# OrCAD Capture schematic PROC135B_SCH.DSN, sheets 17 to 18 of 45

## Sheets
17 17. LPDDR4 INTERFACE: size C; title: SOC DDRSS AND LPDDR4 MEMORY DEVICE INTERFACE
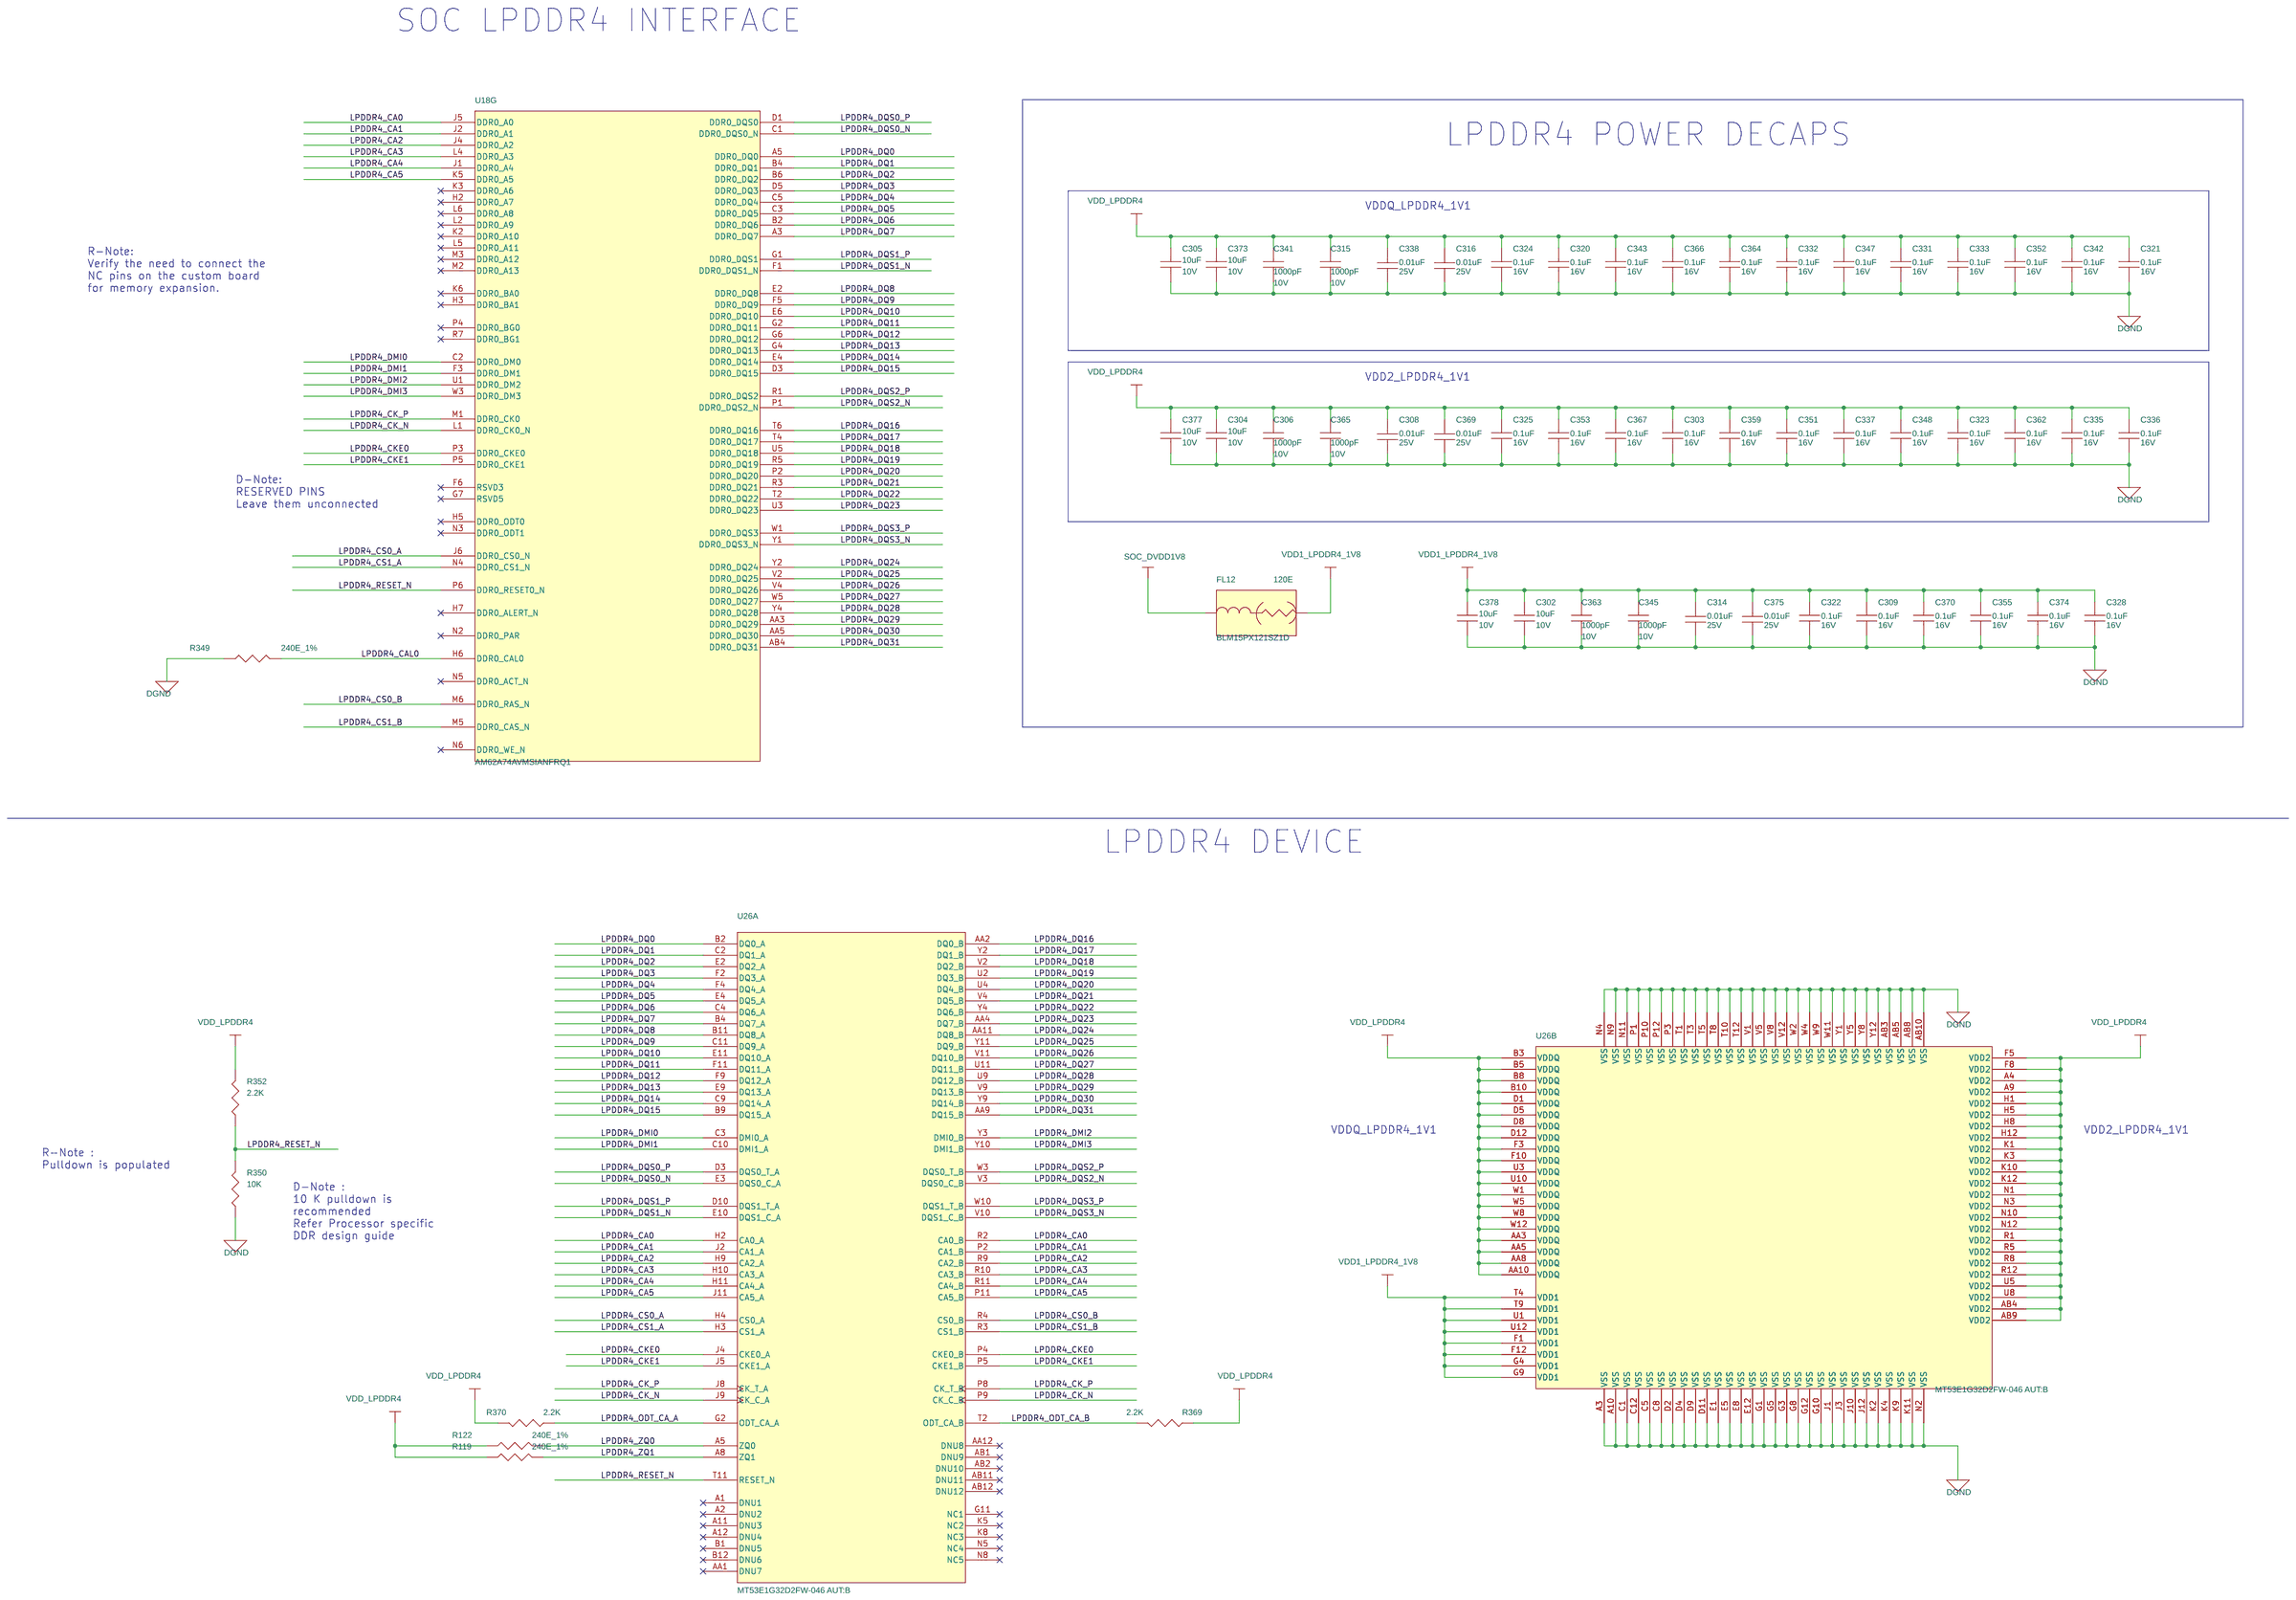
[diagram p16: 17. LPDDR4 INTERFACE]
18 18. M.2 CONNECTOR: size C; title: M.2 INTERFACE AND CONNECTOR
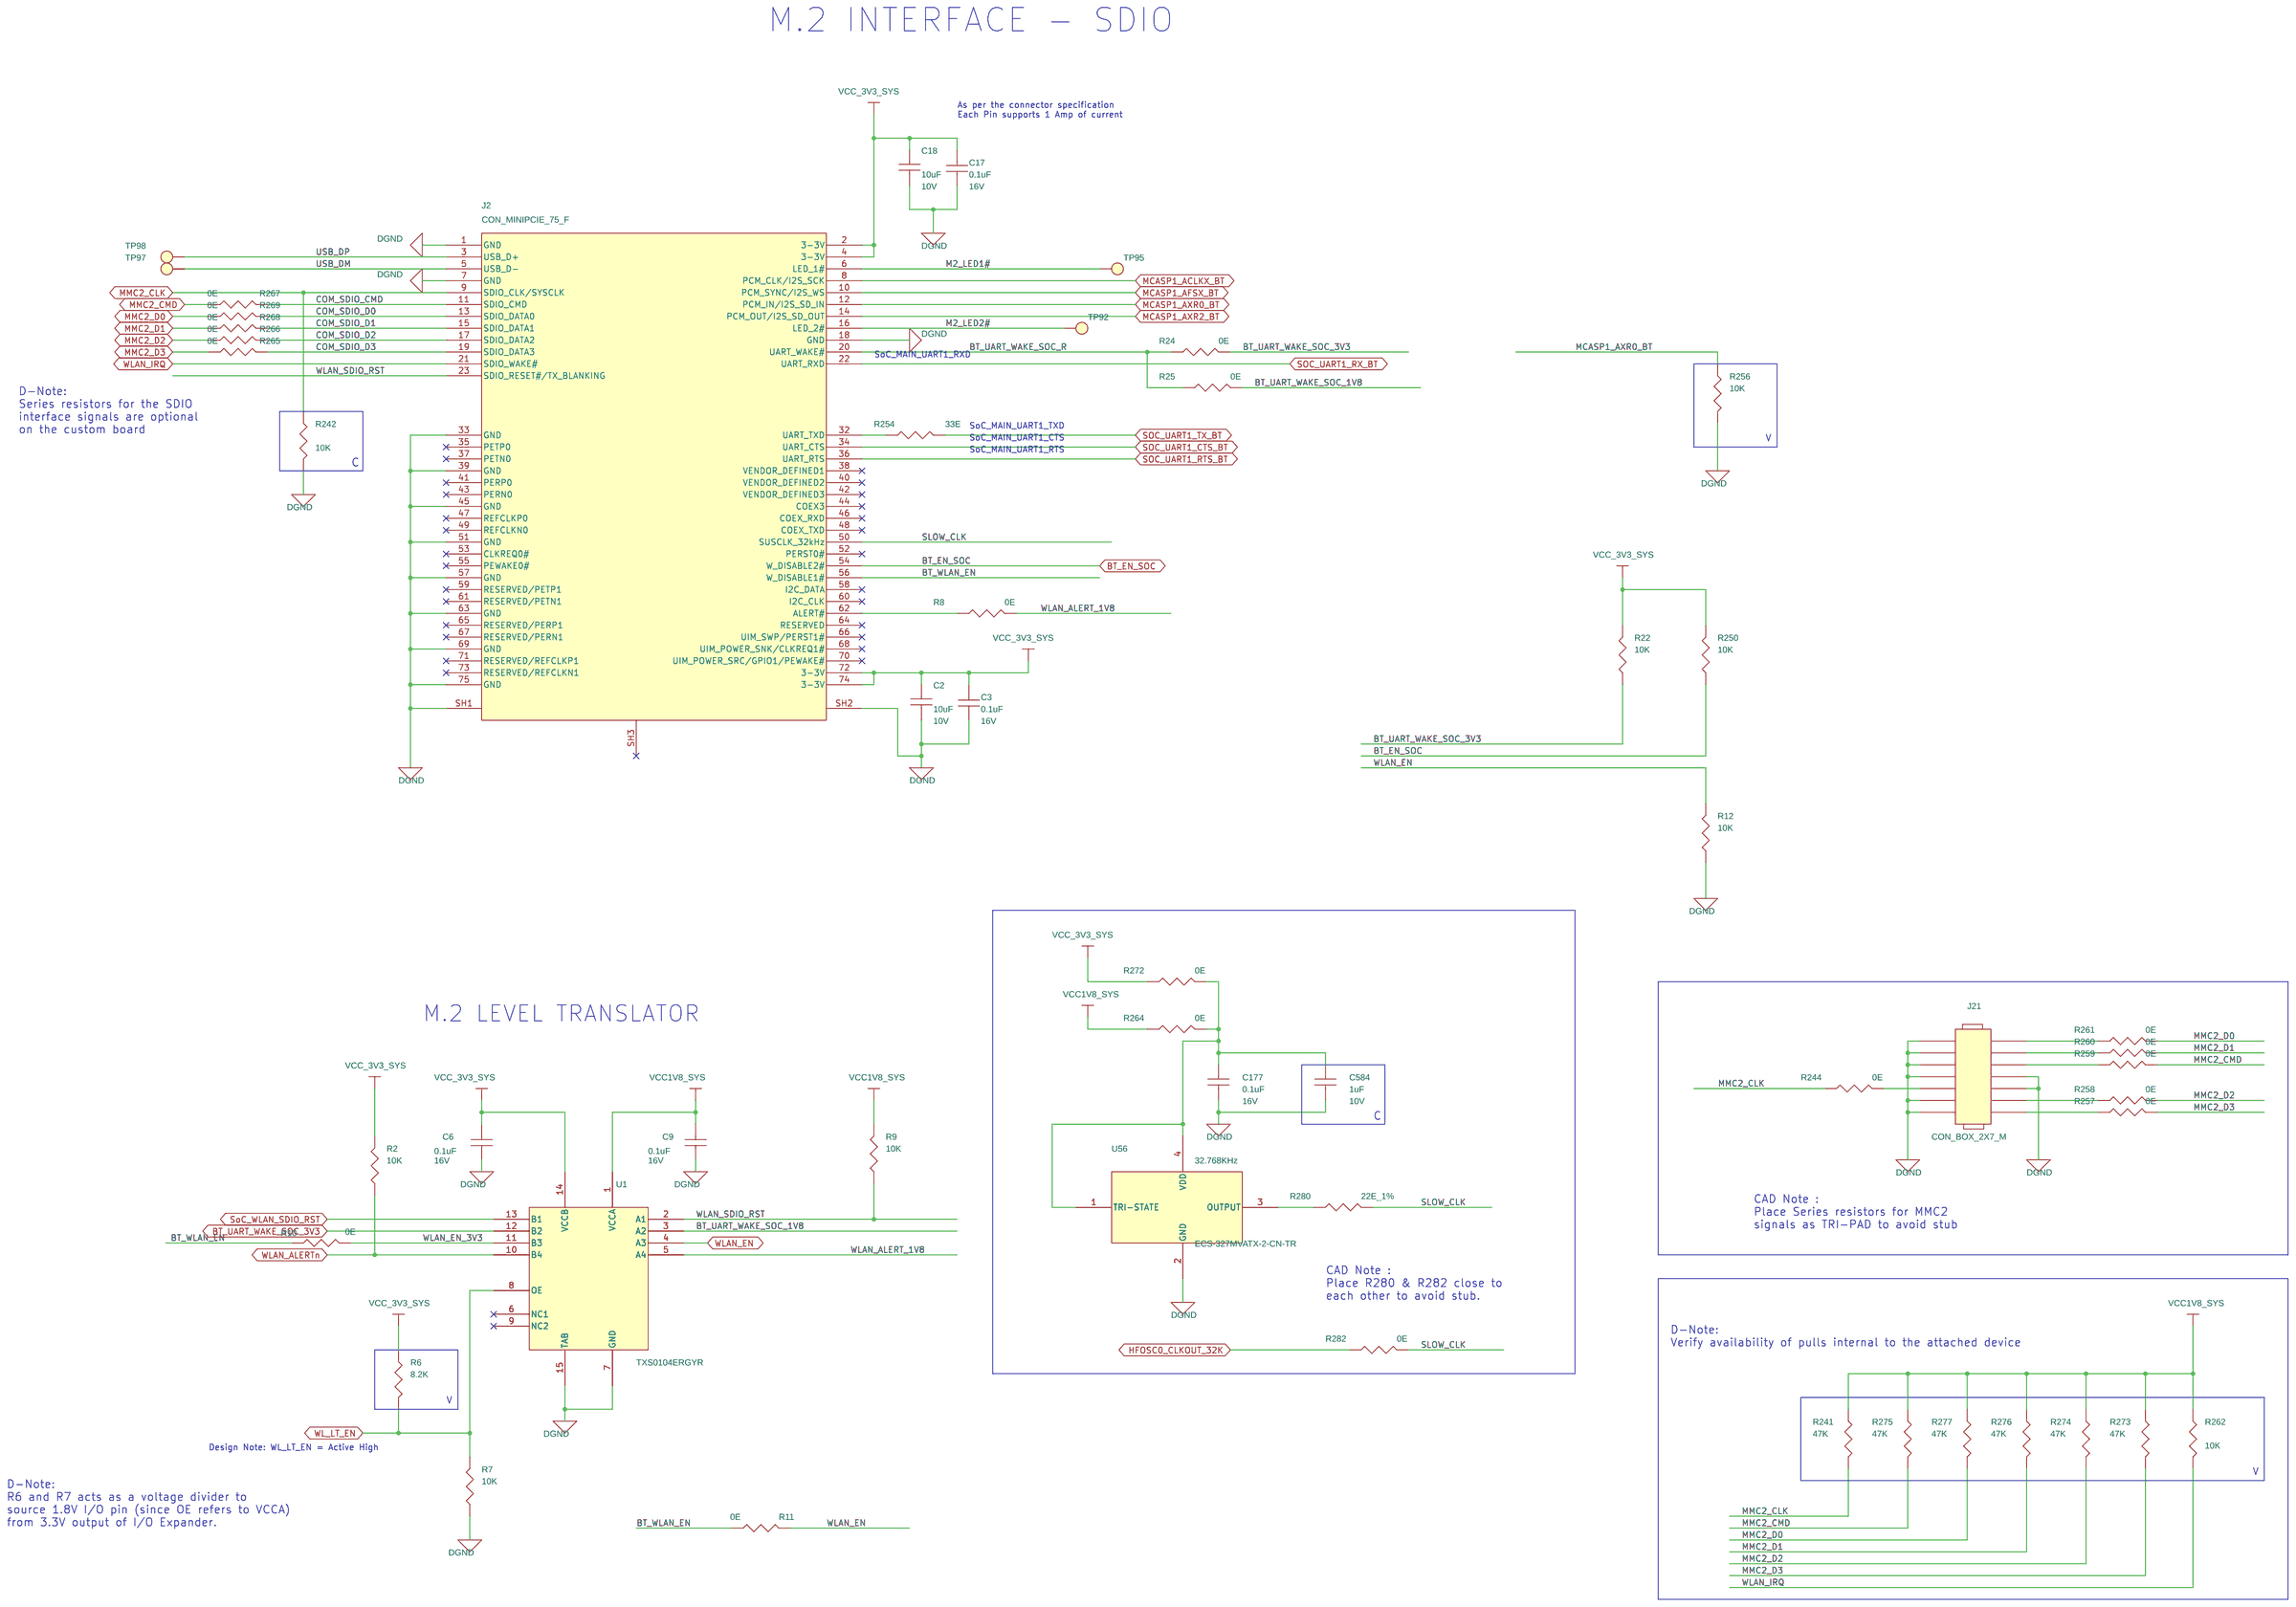
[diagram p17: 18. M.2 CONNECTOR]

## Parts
sheet 17. LPDDR4 INTERFACE
C302  10uF  [CAP0402_0-75]
C303  0.1uF  [CAP0201_0-5]
C304  10uF  [CAP0402_0-75]
C305  10uF  [CAP0402_0-75]
C306  1000pF  [CAP0201_0-5]
C308  0.01uF  [CAP0201_0-5]
C309  0.1uF  [CAP0201_0-5]
C314  0.01uF  [CAP0201_0-5]
C315  1000pF  [CAP0201_0-5]
C316  0.01uF  [CAP0201_0-5]
C320  0.1uF  [CAP0201_0-5]
C321  0.1uF  [CAP0201_0-5]
C322  0.1uF  [CAP0201_0-5]
C323  0.1uF  [CAP0201_0-5]
C324  0.1uF  [CAP0201_0-5]
C325  0.1uF  [CAP0201_0-5]
C328  0.1uF  [CAP0201_0-5]
C331  0.1uF  [CAP0201_0-5]
C332  0.1uF  [CAP0201_0-5]
C333  0.1uF  [CAP0201_0-5]
C335  0.1uF  [CAP0201_0-5]
C336  0.1uF  [CAP0201_0-5]
C337  0.1uF  [CAP0201_0-5]
C338  0.01uF  [CAP0201_0-5]
C341  1000pF  [CAP0201_0-5]
C342  0.1uF  [CAP0201_0-5]
C343  0.1uF  [CAP0201_0-5]
C345  1000pF  [CAP0201_0-5]
C347  0.1uF  [CAP0201_0-5]
C348  0.1uF  [CAP0201_0-5]
C351  0.1uF  [CAP0201_0-5]
C352  0.1uF  [CAP0201_0-5]
C353  0.1uF  [CAP0201_0-5]
C355  0.1uF  [CAP0201_0-5]
C359  0.1uF  [CAP0201_0-5]
C362  0.1uF  [CAP0201_0-5]
C363  1000pF  [CAP0201_0-5]
C364  0.1uF  [CAP0201_0-5]
C365  1000pF  [CAP0201_0-5]
C366  0.1uF  [CAP0201_0-5]
C367  0.1uF  [CAP0201_0-5]
C369  0.01uF  [CAP0201_0-5]
C370  0.1uF  [CAP0201_0-5]
C373  10uF  [CAP0402_0-75]
C374  0.1uF  [CAP0201_0-5]
C375  0.01uF  [CAP0201_0-5]
C377  10uF  [CAP0402_0-75]
C378  10uF  [CAP0402_0-75]
FL12  120E  [EMIFIL_BLM15A_0402_0-6]
R119  240E_1%  [RES0402_0-5]
R122  240E_1%  [RES0402_0-5]
R349  240E_1%  [RES0402_0-5]
R350  10K  [RES0402_0-5]
R352  2.2K  [RES0402_0-5]
R369  2.2K  [RES0402_0-5]
R370  2.2K  [RES0402_0-5]
U26  MT53E1G32D2FW-046 AUT:B  [WFBGA200_MT53E2G32D4DE_400X570_1-2]  (sections A,B)
sheet 18. M.2 CONNECTOR
C2  10uF  [CAP0402_0-75]
C3  0.1uF  [CAP0201_0-5]
C6  0.1uF  [CAP0201_0-5]
C9  0.1uF  [CAP0201_0-5]
C17  0.1uF  [CAP0201_0-5]
C18  10uF  [CAP0402_0-75]
C177  0.1uF  [CAP0201_0-5]
C584  1uF  [CAP0201_0-5]
J2  CON_MINIPCIE_75_F  [CON_MINIPCI75_2199119-4_S_R_S_3-2_2230]
J21  CON_BOX_2X7_M  [CON_BOX2X7_3020-14-0300-00_P_S_S_10-4]
R2  10K  [RES0201_0-5]
R6  8.2K  [RES0201_0-5]
R7  10K  [RES0201_0-5]
R8  0E  [RES0201_0-5]
R9  10K  [RES0201_0-5]
R10  0E  [RES0201_0-5]
R11  0E  [RES0201_0-5]
R12  10K  [RES0201_0-5]
R22  10K  [RES0201_0-5]
R24  0E  [RES0201_0-5]
R25  0E  [RES0201_0-5]
R241  47K  [RES0201_0-5]
R242  10K  [RES0201_0-5]
R244  0E  [RES0201_0-5]
R250  10K  [RES0201_0-5]
R254  33E  [RES0201_0-5]
R256  10K  [RES0402_0-5]
R257  0E  [RES0201_0-5]
R258  0E  [RES0201_0-5]
R259  0E  [RES0201_0-5]
R260  0E  [RES0201_0-5]
R261  0E  [RES0201_0-5]
R262  10K  [RES0201_0-5]
R264  0E  [RES0201_0-5]
R265  0E  [RES0201_0-5]
R266  0E  [RES0201_0-5]
R267  0E  [RES0201_0-5]
R268  0E  [RES0201_0-5]
R269  0E  [RES0201_0-5]
R272  0E  [RES0201_0-5]
R273  47K  [RES0201_0-5]
R274  47K  [RES0201_0-5]
R275  47K  [RES0201_0-5]
R276  47K  [RES0201_0-5]
R277  47K  [RES0201_0-5]
R280  22E_1%  [RES0201_0-5]
R282  0E  [RES0201_0-5]
TP92  TP20_SMD  [TP20_SMD]
TP95  TP20_SMD  [TP20_SMD]
TP97  TP20_SMD  [TP20_SMD]
TP98  TP20_SMD  [TP20_SMD]
U1  TXS0104ERGYR  [QFN14_19-68_145X145]
U56  32.768KHz  [OSC4_ECS-327MVATX-2_100X80_SMD_1]
sheet 34. MCU HEADER
U18  AM62A74AVMSIANFRQ1  [FBGA484_31-49_710X710_2-7]  (sections A,B,C,D,E,F,G,H,I,J,K,L,M,N,O,P,Q)

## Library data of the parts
C2 C18 C302 C304 C305 C373 C377 C378 = CAP: CAP CERAMIC 10uF 10V 20% X5R 0402; Chkd/date: PRADEEP/130623; Crtd /date: PRADEEP/130623; Custom_Duty: 15%; Customs_HS_Code: 85322990; Distributor_name: NA; Distributor_part_number: NA; Footprint Path: Y:\MIS_DATABASE\Library\ALTIUM_TOOL\PCB_FOOTPRINTS\Altium_Footprint_Lib.PcbLib; Height: 0.55MM; Library Path: Y:\MIS_DATABASE\Library\ALTIUM_TOOL\SCHEMATICS_PARTS\MS_DISCRETE_Library.schlib; Mfr_name: MURATA; Mfr_part_number: GRM155R61A106ME18; Mistral Part No: 120022060018-R; Package: 0402; Part_type: CAPACITORS\CERAMIC; Project: AM62P_SK; RoHS: RoHS; Temperature: -55°C+85°C; Tolerance: 20%; Voltage: 10V; Wattage: NA; Weight: 6mg; Datasheet: Y:\MIS_DATABASE\DATASHEETS\CAPACITORS\MURATA-GXX-SER_NOV17.PDF
C303 C309 C320-C325 C328 C331-C333 C335-C337 C342 C343 C347 C348 C351-C353 C355 C359 C362 C364 C366 C367 C370 C374 = CAP: CAP CERAMIC 0.1uF 16V 10% X5R 0201; Chkd/date: PRADEEP/130623; Crtd /date: PRADEEP/130623; Custom_Duty: 15%; Customs_HS_Code: 85322990; Distributor_name: NA; Distributor_part_number: NA; Footprint Path: Y:\MIS_DATABASE\Library\ALTIUM_TOOL\PCB_FOOTPRINTS\Altium_Footprint_Lib.PcbLib; Height: 0.33MM; Library Path: Y:\MIS_DATABASE\Library\ALTIUM_TOOL\SCHEMATICS_PARTS\MS_DISCRETE_Library.schlib; Mfr_name: MURATA; Mfr_part_number: GRT033R61C104KE01; Mistral Part No: 120022060019-R; Package: 0201; Part_type: CAPACITORS\CERAMIC; Project: AM62P_SK; RoHS: RoHS; Temperature: -55°C+85°C; Tolerance: 10%; Voltage: 16V; Wattage: NA; Weight: 0.33mg; Datasheet: Y:\MIS_DATABASE\DATASHEETS\CAPACITORS\GRT033R61C104KE01XX.PDF
C306 C315 C341 C345 C363 C365 = CAP: CAP CERAMIC 1000pF 10V 10% X7R 0201; Chkd/date: VASANTHA/010117; Crtd /date: MAZHAR/160807; Custom_Duty: 15%; Customs_HS_Code: 85322990; Distributor_name: DIGIKEY; Distributor_part_number: 0201ZC102KAT2A-ND; Footprint Path: Y:\MIS_DATABASE\Library\ALTIUM_TOOL\PCB_FOOTPRINTS\Altium_Footprint_Lib.PcbLib; Height: 0.33MM; Library Path: Y:\MIS_DATABASE\Library\ALTIUM_TOOL\SCHEMATICS_PARTS\MS_DISCRETE_Library.schlib; Mfr_name: AVX CORPORATION; Mfr_part_number: 0201ZC102KAT2A; Mistral Part No: 120009030143-R; Package: 0201; Part_type: CAPACITORS\CERAMIC; Project: V8TS; RoHS: RoHS; Temperature: -55°C+125°C; Tolerance: 10%; Voltage: 10V; Wattage: NA; Weight: 0.17mg; Datasheet: Y:\MIS_DATABASE\DATASHEETS\CAPACITORS\AVX_MLC.PDF
C308 C314 C316 C338 C369 C375 = CAP: CAP CERAMIC 0.01uF 25V 10% X5R AUTO 0201; Chkd/date: MANIRAJA/311221; Crtd /date: ALVY/301221; Custom_Duty: 15%; Customs_HS_Code: 85322990; Distributor_name: MOUSER; Distributor_part_number: 81-GRT033R61E103KE1D; Footprint Path: Y:\MIS_DATABASE\Library\ALTIUM_TOOL\PCB_FOOTPRINTS\Altium_Footprint_Lib.PcbLib; Height: 0.33MM; Library Path: Y:\MIS_DATABASE\Library\ALTIUM_TOOL\SCHEMATICS_PARTS\MS_DISCRETE_Library.schlib; Mfr_name: MURATA; Mfr_part_number: GRT033R61E103KE01D; Mistral Part No: 120021120019-R; Package: 0201; Part_type: CAPACITORS\CERAMIC; Project: AM62Q_SKEVM_BRD; RoHS: RoHS; Temperature: -55°C+85°C; Tolerance: 10%; Voltage: 25V; Wattage: NA; Weight: 0.33mg; Datasheet: Y:\MIS_DATABASE\DATASHEETS\CAPACITORS\GRT033R61E103KE01.PDF
FL12 = EMIFILTER_IND: IND FERRITE BEAD CHIP 120E 2A 0402; Crtd /date: SHANKARI/100425; Custom_Duty: 24%; Customs_HS_Code: 85369090; Distributor_name: DIGIKEY; Distributor_part_number: 490-16505-1-ND; Footprint Path: Y:\MIS_DATABASE\Library\ALTIUM_TOOL\PCB_FOOTPRINTS\Altium_Footprint_Lib.PcbLib; Height: 0.55MM; Library Path: Y:\MIS_DATABASE\Library\ALTIUM_TOOL\SCHEMATICS_PARTS\MS_FILTER_Library.schlib; Mfr_name: MURATA; Mfr_part_number: BLM15PX121SZ1D; Mistral Part No: 130025040021-R; Package: 0402; Part_type: INDUCTOR; Project: XWRL6844_EVM_PROTO; RoHS: RoHS; Temperature: -55°C+125°C; Tolerance: 25%; Voltage: NA; Wattage: NA; Weight: NA; Datasheet: Y:\MIS_DATABASE\DATASHEETS\DISCRETES\INDUCTORS\BLM15PX121SZ1D.PDF
R119 R122 R349 = RESISTOR: RES 240E 1/10W 1% 0402; Chkd/date: MAZHAR/150611; Crtd /date: BAVISH/020611; Custom_Duty: 15%; Customs_HS_Code: 85332119; Distributor_name: DIGIKEY; Distributor_part_number: P240LCT-ND; Footprint Path: Y:\MIS_DATABASE\Library\ALTIUM_TOOL\PCB_FOOTPRINTS\Altium_Footprint_Lib.PcbLib; Height: 0.40MM; Library Path: Y:\MIS_DATABASE\Library\ALTIUM_TOOL\SCHEMATICS_PARTS\MS_DISCRETE_Library.schlib; Mfr_name: PANASONIC-ECG; Mfr_part_number: ERJ-2RKF2400X; Mistral Part No: 110011060017-R; Package: 0402; Part_type: RESISTORS\FIXED; Project: AM4515_EVM_LCD; RoHS: RoHS; Temperature: -55°C+155°C; Tolerance: 1%; Voltage: NA; Wattage: 1/10W; Weight: 0.8mg; Datasheet: Y:\MIS_DATABASE\DATASHEETS\RESISTORS\PAN-ERJSER_NOV17.PDF
R350 = RESISTOR: RES 10K 1/16W 5% 0402; Chkd/date: VASANTHA/061216; Crtd /date: MAZHAR/230805; Custom_Duty: 15%; Customs_HS_Code: 85332119; Distributor_name: DIGIKEY; Distributor_part_number: 311-10KJRCT-ND; Footprint Path: Y:\MIS_DATABASE\Library\ALTIUM_TOOL\PCB_FOOTPRINTS\Altium_Footprint_Lib.PcbLib; Height: 0.40MM; Library Path: Y:\MIS_DATABASE\Library\ALTIUM_TOOL\SCHEMATICS_PARTS\MS_DISCRETE_Library.schlib; Mfr_name: YAGEO AMERICA; Mfr_part_number: RC0402JR-0710KL; Mistral Part No: 110011060021-R; Package: 0402; Part_type: RESISTORS\FIXED; Project: HSE; RoHS: RoHS; Temperature: -55°C+155°C; Tolerance: 5%; Voltage: NA; Wattage: 1/16W; Weight: 0.65mg; Datasheet: Y:\MIS_DATABASE\DATASHEETS\RESISTORS\RCXXXXL-SER_MAR18.PDF
R352 R369 R370 = RESISTOR: RES 2.2K 1/16W 5% 0402; Chkd/date: VASANTHA/061216; Crtd /date: BAVISH/021210; Custom_Duty: 15%; Customs_HS_Code: 85332119; Distributor_name: DIGIKEY; Distributor_part_number: 311-2.2KJRCT-ND; Footprint Path: Y:\MIS_DATABASE\Library\ALTIUM_TOOL\PCB_FOOTPRINTS\Altium_Footprint_Lib.PcbLib; Height: 0.40MM; Library Path: Y:\MIS_DATABASE\Library\ALTIUM_TOOL\SCHEMATICS_PARTS\MS_DISCRETE_Library.schlib; Mfr_name: YAGEO AMERICA; Mfr_part_number: RC0402JR-072K2L; Mistral Part No: 110010120018-R; Package: 0402; Part_type: RESISTORS\FIXED; Project: TE4; RoHS: RoHS; Temperature: -55°C+155°C; Tolerance: 5%; Voltage: NA; Wattage: 1/16W; Weight: 0.65mg; Datasheet: Y:\MIS_DATABASE\DATASHEETS\RESISTORS\RCXXXXL-SER_MAR18.PDF
U26 = MT53D1024M32D4DT_VFBGA200: IC 4GB AUTO LPDDR4/LPDDR4x SDRAM TFBGA200; Crtd /date: TAMILARASU/141122; Custom_Duty: 15%; Customs_HS_Code: 85423100; Distributor_name: NA; Distributor_part_number: NA; Footprint Path: Y:\MIS_DATABASE\Library\ALTIUM_TOOL\PCB_FOOTPRINTS\Altium_Footprint_Lib.PcbLib; Height: 1.14MM; Library Path: Y:\MIS_DATABASE\Library\ALTIUM_TOOL\SCHEMATICS_PARTS\MS_MISCMEMORY_Library.schlib; Mfr_name: MICRON; Mistral Part No: 141122110001-R; Package: TFBGA200; Part_type: ICS\DIGITAL\MEMORY; Project: AM62A_EVM_BRD; RoHS: RoHS; Temperature: -40°C+125°C; Tolerance: NA; Voltage: NA; Wattage: NA; Weight: NA; Datasheet: Y:\MIS_DATABASE\DATASHEETS\ICS\MEMORY\MT53EX-A-AUTO-SER.PDF
C3 C6 C9 C17 C177 = CAP: CAP CERAMIC 0.1uF 16V 10% X5R 0201; Alt_Mfr_name: YAGEO AMERICA; Alt_Mfr_part_number: CC0402KRX5R8BB104; Chkd/date: PRADEEP/130623; Crtd /date: PRADEEP/130623; Custom_Duty: 15%; Customs_HS_Code: 85322990; Distributor_name: NA; Distributor_part_number: NA; Footprint Path: Y:\MIS_DATABASE\Library\ALTIUM_TOOL\PCB_FOOTPRINTS\Altium_Footprint_Lib.PcbLib; Height: 0.33MM; Library Path: Y:\MIS_DATABASE\Library\ALTIUM_TOOL\SCHEMATICS_PARTS\MS_DISCRETE_Library.schlib; Mfr_name: MURATA; Mfr_part_number: GRT033R61C104KE01; Mistral Part No: 120022060019-R; Package: 0201; Part_type: CAPACITORS\CERAMIC; Project: AM62P_SK; RoHS: RoHS; Temperature: -55°C+85°C; Tolerance: 10%; Voltage: 16V; Wattage: NA; Weight: 0.33mg; Datasheet: Y:\MIS_DATABASE\DATASHEETS\CAPACITORS\GRT033R61C104KE01XX.PDF
C584 = CAP: CAP CERAMIC 1uF 10V 20% X6S 0201; Chkd/date: PRADEEP/130623; Crtd /date: PRADEEP/130623; Custom_Duty: 15%; Customs_HS_Code: 85322990; Distributor_name: DIGIKEY; Distributor_part_number: 490-GRT033C81A105ME13DTR-ND; Footprint Path: Y:\MIS_DATABASE\Library\ALTIUM_TOOL\PCB_FOOTPRINTS\Altium_Footprint_Lib.PcbLib; Height: 0.39MM; Library Path: Y:\MIS_DATABASE\Library\ALTIUM_TOOL\SCHEMATICS_PARTS\MS_DISCRETE_Library.schlib; Mfr_name: MURATA; Mfr_part_number: GRT033C81A105ME13D; Mistral Part No: 120022060020-R; Package: 0201; Part_type: CAPACITORS\CERAMIC; Project: AM62P_SK; RoHS: RoHS; Temperature: -55°C+105°C; Tolerance: 20%; Voltage: 10V; Wattage: NA; Weight: NA; Datasheet: Y:\MIS_DATABASE\DATASHEETS\CAPACITORS\GRT033C81A105ME13D.PDF
J2 = CON_PCI_75_2199119-4_2230: CON MINIPCI 75POS 0.50MM PITCH FEMALE RT SMD; Chkd/date: ALVY/300521; Crtd /date: ALVY/300521; Custom_Duty: 24%; Customs_HS_Code: 85369090; Distributor_name: DIGIKEY; Distributor_part_number: A115900CT-ND; Footprint Path: Y:\MIS_DATABASE\Library\ALTIUM_TOOL\PCB_FOOTPRINTS\Altium_Footprint_Lib.PcbLib; Height: 3.20MM; Library Path: Y:\MIS_DATABASE\Library\ALTIUM_TOOL\SCHEMATICS_PARTS\MS_CONNECTOR_Library.schlib; Mfr_name: TE CONNECTIVITY; Mfr_part_number: 2199119-4_2230; Mistral Part No: 150021030016-R; Package: SMD; Part_type: CONNECTOR\PCI; Project: VOLTA_CHARGER V5; RoHS: RoHS; Temperature: -40°C+80°C; Tolerance: NA; Voltage: NA; Wattage: NA; Weight: 506mg; Datasheet: Y:\MIS_DATABASE\DATASHEETS\CONNECTORS\2199119.PDF
J21 = HEADER_7X2: CON BOX 2X7 2.54MM PITCH MALE ST SMD; Chkd/date: MANIRAJA/080921; Crtd /date: ALVY/080921; Custom_Duty: 24%; Customs_HS_Code: 85369090; Distributor_name: DIGIKEY; Distributor_part_number: 1175-1622-ND; Footprint Path: Y:\MIS_DATABASE\Library\ALTIUM_TOOL\PCB_FOOTPRINTS\Altium_Footprint_Lib.PcbLib; Height: 10.32MM; Library Path: Y:\MIS_DATABASE\Library\ALTIUM_TOOL\SCHEMATICS_PARTS\MS_CONNECTOR_Library.schlib; Mfr_name: CnC TECH; Mfr_part_number: 3020-14-0300-00; Mistral Part No: 150021090012-R; Package: SMD; Part_type: CONNECTOR\BOX HEADERS; Project: TI_AM335x SK_BRD; RoHS: RoHS; Temperature: -40°C+105°C; Tolerance: NA; Voltage: NA; Wattage: NA; Weight: NA; Datasheet: Y:\MIS_DATABASE\DATASHEETS\CONNECTORS\3020-XX-0300-00.PDF
R2 R7 R9 R12 R22 R242 R250 R262 = RESISTOR: RES 10K 1/20W 5% 0201; Chkd/date: MANIRAJA/050517; Crtd /date: MANIRAJA/050517; Custom_Duty: 15%; Customs_HS_Code: 85332119; Distributor_name: DIGIKEY; Distributor_part_number: 311-10KNCT-ND; Footprint Path: Y:\MIS_DATABASE\Library\ALTIUM_TOOL\PCB_FOOTPRINTS\Altium_Footprint_Lib.PcbLib; Height: 0.26MM; Library Path: Y:\MIS_DATABASE\Library\ALTIUM_TOOL\SCHEMATICS_PARTS\MS_DISCRETE_Library.schlib; Mfr_name: YAGEO AMERICA; Mfr_part_number: RC0201JR-0710KL; Mistral Part No: 110010070051-R; Package: 0201; Part_type: RESISTORS\FIXED; Project: GOLDEN-I LITE; RoHS: RoHS; Temperature: -55°C+125°C; Tolerance: 5%; Voltage: NA; Wattage: 1/20W; Weight: 0.17mg; Datasheet: Y:\MIS_DATABASE\DATASHEETS\RESISTORS\RCXXXXL-SER_MAR18.PDF
R6 = RESISTOR: RES 8.2K 1/20W 5% 0201; Chkd/date: PRADEEP/100626; Crtd /date: SHANKARI/100626; Custom_Duty: 15%; Customs_HS_Code: 85332119; Distributor_name: DIGIKEY; Distributor_part_number: YAG2366CT-ND; Footprint Path: Y:\MIS_DATABASE\Library\ALTIUM_TOOL\PCB_FOOTPRINTS\Altium_Footprint_Lib.PcbLib; Height: 0.26MM; Library Path: Y:\MIS_DATABASE\Library\ALTIUM_TOOL\SCHEMATICS_PARTS\MS_DISCRETE_Library.schlib; Mfr_name: YAGEO; Mfr_part_number: RC0201JR-078K2L; Mistral Part No: 110026060023-R; Package: 0201; Part_type: RESISTORS\FIXED; Project: AM62X_FULTON_REV-B; RoHS: RoHS; Temperature: -55°C+125°C; Tolerance: 0.05; Voltage: NA; Wattage: 1/20W; Weight: NA; Datasheet: Y:\MIS_DATABASE\DATASHEETS\RESISTORS\RC0201JR-078K2L.PDF
R8 R10 R11 R24 R25 R244 R257-R261 R264-R269 R272 R282 = RESISTOR: RES 0E 1/20W 5% 0201; Chkd/date: NAVEED/301214; Crtd /date: MUDDU/120710; Custom_Duty: 15%; Customs_HS_Code: 85332119; Distributor_name: DIGIKEY; Distributor_part_number: 311-0.0NCT-ND; Footprint Path: Y:\MIS_DATABASE\Library\ALTIUM_TOOL\PCB_FOOTPRINTS\Altium_Footprint_Lib.PcbLib; Height: 0.26MM; Library Path: Y:\MIS_DATABASE\Library\ALTIUM_TOOL\SCHEMATICS_PARTS\MS_DISCRETE_Library.schlib; Mfr_name: YAGEO AMERICA; Mfr_part_number: RC0201JR-070RL; Mistral Part No: 110010070067-R; Package: 0201; Part_type: RESISTORS\FIXED; Project: PB_BUGBASE; RoHS: RoHS; Temperature: -55°C+125°C; Tolerance: 5%; Voltage: NA; Wattage: 1/20W; Weight: 0.17mg; Datasheet: Y:\MIS_DATABASE\DATASHEETS\RESISTORS\RCXXXXL-SER_MAR18.PDF
R241 R273-R277 = RESISTOR: RES 47K 1/20W 5% 0201; Chkd/date: MAZHAR/121207; Crtd /date: USMAN/121207; Custom_Duty: 15%; Customs_HS_Code: 85332119; Distributor_name: DIGIKEY; Distributor_part_number: P47KAGCT-ND; Footprint Path: Y:\MIS_DATABASE\Library\ALTIUM_TOOL\PCB_FOOTPRINTS\Altium_Footprint_Lib.PcbLib; Height: 0.26MM; Library Path: Y:\MIS_DATABASE\Library\ALTIUM_TOOL\SCHEMATICS_PARTS\MS_DISCRETE_Library.schlib; Mfr_name: PANASONIC-ECG; Mfr_part_number: ERJ-1GEJ473C; Mistral Part No: 110009030881-R; Package: 0201; Part_type: RESISTORS\FIXED; Project: SD_WATERLOO; RoHS: RoHS; Temperature: -55°C+125°C; Tolerance: 5%; Voltage: NA; Wattage: 1/20W; Weight: 0.15mg; Datasheet: Y:\MIS_DATABASE\DATASHEETS\RESISTORS\PAN-ERJXGE-FEB06.PDF
R254 = RESISTOR: RES 33E 1/20W 5% 0201; Chkd/date: MANIRAJA/050517; Crtd /date: MANIRAJA/050517; Custom_Duty: 15%; Customs_HS_Code: 85332119; Distributor_name: DIGIKEY; Distributor_part_number: 311-33NCT-ND; Footprint Path: Y:\MIS_DATABASE\Library\ALTIUM_TOOL\PCB_FOOTPRINTS\Altium_Footprint_Lib.PcbLib; Height: 0.26MM; Library Path: Y:\MIS_DATABASE\Library\ALTIUM_TOOL\SCHEMATICS_PARTS\MS_DISCRETE_Library.schlib; Mfr_name: YAGEO AMERICA; Mfr_part_number: RC0201JR-0733RL; Mistral Part No: 110010070052-R; Package: 0201; Part_type: RESISTORS\FIXED; Project: GOLDEN-I LITE; RoHS: RoHS; Temperature: -55°C+125°C; Tolerance: 5%; Voltage: NA; Wattage: 1/20W; Weight: 0.17mg; Datasheet: Y:\MIS_DATABASE\DATASHEETS\RESISTORS\RCXXXXL-SER_MAR18.PDF
R256 = RESISTOR: RES 10K 1/16W 5% 0402; Chkd/date: MANIRAJA/120219; Crtd /date: MANIRAJA/120219; Custom_Duty: 15%; Customs_HS_Code: 85332119; Distributor_name: DIGIKEY; Distributor_part_number: 541-10KJCT-ND; Footprint Path: Y:\MIS_DATABASE\Library\ALTIUM_TOOL\PCB_FOOTPRINTS\Altium_Footprint_Lib.PcbLib; Height: 0.40MM; Library Path: Y:\MIS_DATABASE\Library\ALTIUM_TOOL\SCHEMATICS_PARTS\MS_DISCRETE_Library.schlib; Mfr_name: VISHAY; Mfr_part_number: CRCW040210K0JNED; Mistral Part No: 110011060021-R; Package: 0402; Part_type: RESISTORS\FIXED; Project: NEXTNAV_ORBIT_MODULE; RoHS: RoHS; Temperature: -55°C+155°C; Tolerance: 5%; Voltage: NA; Wattage: 1/16W; Weight: 0.65mg; Datasheet: Y:\MIS_DATABASE\DATASHEETS\RESISTORS\CRCW0603.PDF
R280 = RESISTOR: RES 22E 1/20W 1% 0201; Chkd/date: MANIRAJA/080319; Crtd /date: ALVY/080319; Custom_Duty: 15%; Customs_HS_Code: 85332119; Distributor_name: DIGIKEY; Distributor_part_number: YAG2518CT-ND; Footprint Path: Y:\MIS_DATABASE\Library\ALTIUM_TOOL\PCB_FOOTPRINTS\Altium_Footprint_Lib.PcbLib; Height: 0.26MM; Library Path: Y:\MIS_DATABASE\Library\ALTIUM_TOOL\SCHEMATICS_PARTS\MS_DISCRETE_Library.schlib; Mfr_name: YAGEO AMERICA; Mfr_part_number: RC0201FR-0722RL; Mistral Part No: 110009030522-R; Package: 0201; Part_type: RESISTORS\FIXED; Project: AM654x_SOM; RoHS: RoHS; Temperature: -55°C+125°C; Tolerance: 1%; Voltage: NA; Wattage: 1/20W; Weight: 0.17mg; Datasheet: Y:\MIS_DATABASE\DATASHEETS\RESISTORS\RCXXXXL-SER_MAR18.PDF
TP92 TP95 TP97 TP98 = TESTPOINT: TESTPOINT CIR 20 SMD; Chkd/date: SHREESHAIL/171006; Crtd /date: MAZHAR/171006; Custom_Duty: NA; Customs_HS_Code: NA; Distributor_name: NA; Distributor_part_number: NA; Footprint Path: Y:\MIS_DATABASE\Library\ALTIUM_TOOL\PCB_FOOTPRINTS\Altium_Footprint_Lib.PcbLib; Height: NA; Library Path: Y:\MIS_DATABASE\Library\ALTIUM_TOOL\SCHEMATICS_PARTS\MS_DISCRETE_Library.schlib; MECHANICAL 3D STEP FILE: NA; Mfr_name: LOCAL; Mistral Part No: NA; Package: SMD; Project: BT MODULE_CSRBC04; RoHS: NA; Temperature: NA; Tolerance: NA; Voltage: NA; Wattage: NA; Weight: NA; Datasheet: NA
U1 = TXS0104ERGYR_QFN14: IC 4-BIT BIDIRECTIONAL VOLTAGE-LEVEL TRANSLATOR QFN14; Chkd/date: SHREESHAIL/170108; Crtd /date: SHREESHAIL/170108; Custom_Duty: 15%; Customs_HS_Code: 85423100; Distributor_name: DIGIKEY; Distributor_part_number: 296-20698-1-ND; Height: 1.00MM; Mfr_name: TEXAS INSTRUMENTS; Mistral Part No: 141009030362-R; Package: QFN14; Part_type: ICS\INTERFACE; Project: HS100RD; RoHS: Sb/ Br FREE; Datasheet: Y:\MIS_DATABASE\DATASHEETS\ICS\INTERFACE\TXS0104E.PDF
U56 = OSC4_ASFL3: OSC 32.768KHz CMOS SMD; Chkd/date: ALVY/030620; Crtd /date: MANIRAJA/030620; Custom_Duty: 24%; Customs_HS_Code: 85437099; Distributor_name: DIGIKEY; Distributor_part_number: XC3154CT-ND; Footprint Path: Y:\MIS_DATABASE\Library\ALTIUM_TOOL\PCB_FOOTPRINTS\Altium_Footprint_Lib.PcbLib; Height: 1.00MM; Library Path: Y:\MIS_DATABASE\Library\ALTIUM_TOOL\SCHEMATICS_PARTS\MS_DISCRETE_Library.schlib; Mfr_name: ECS INC; Mfr_part_number: ECS-327MVATX-2-CN-TR; Mistral Part No: 130020060007-R; Package: SMD; Part_type: OSCILLATORS; Project: JETSON_CARRIER_BRD; RoHS: RoHS; Temperature: -40°C+85°C; Tolerance: NA; Voltage: NA; Wattage: NA; Weight: NA; Datasheet: Y:\MIS_DATABASE\DATASHEETS\MISC\CRY_OSC\ECS-327MVATX.PDF
U18 = AM62A-EVM_SOC_FCBGA484: IC AM62A SK EVM SoC MICROPROCESSOR FCBGA484; Chkd/date: PRADEEP/120225; Crtd /date: SHANKARI/120225; Custom_Duty: 15%; Customs_HS_Code: 85369090; Distributor_name: NA; Distributor_part_number: NA; Footprint Path: Y:\MIS_DATABASE\Library\ALTIUM_TOOL\PCB_FOOTPRINTS\Altium_Footprint_Lib.PcbLib; Height: 2.65MM; Library Path: Y:\MIS_DATABASE\Library\ALTIUM_TOOL\SCHEMATICS_PARTS\MS_MICROPROCESSOR_Library.schlib; Library Ref: AM62A-EVM_SoC_FCBGA484; Mfr_name: TEXAS INSTRUMENTS; Mistral Part No: 141225020003-R; Package: FCBGA484; Part_type: ICS\DIGITAL\MICROPROCESSOR; Project: AM62A_SK_EVM; RoHS: NA; Temperature: NA; Tolerance: NA; Voltage: NA; Wattage: NA; Weight: NA; Datasheet: Y:\MIS_DATABASE\DATASHEETS\ICS\DIGITAL\MICROCONTROLLER\AM62A_SK_EVM.PDF

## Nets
DGND: C2.2 C3.1 C6.1 C9.1 C17.1 C18.2 C177.2 C302.2 C303.2 C304.2 C305.2 C306.2 C308.1 C309.2 C314.1 C315.2 C316.1 C320.2 C321.2 C322.2 C323.2 C324.2 C325.2 C328.2 C331.2 C332.2 C333.2 C335.2 C336.2 C337.2 C338.1 C341.2 C342.2 C343.2 C345.2 C347.2 C348.2 C351.2 C352.2 C353.2 C355.2 C359.2 C362.2 C363.2 C364.2 C365.2 C366.2 C367.2 C369.1 C370.2 C373.2 C374.2 C375.1 C377.2 C378.2 C584.2 J2.1(GND) J2.7(GND) J2.18(GND) J2.33(GND) J2.39(GND) J2.45(GND) J2.51(GND) J2.57(GND) J2.63(GND) J2.69(GND) J2.75(GND) J2.SH1 J2.SH2 J21.1 J21.3 J21.5 J21.7 J21.8 J21.10 J21.11 J21.13 R7.1 R12.1 R242.2 R256.2 R349.2 R350.1 U1.7(GND) U1.15(TAB) U26.A3(VSS) U26.A10(VSS) U26.AB3(VSS) U26.AB5(VSS) U26.AB8(VSS) U26.AB10(VSS) U26.C1(VSS) U26.C5(VSS) U26.C8(VSS) U26.C12(VSS) U26.D2(VSS) U26.D4(VSS) U26.D9(VSS) U26.D11(VSS) U26.E1(VSS) U26.E5(VSS) U26.E8(VSS) U26.E12(VSS) U26.G1(VSS) U26.G3(VSS) U26.G5(VSS) U26.G8(VSS) U26.G10(VSS) U26.G12(VSS) U26.J1(VSS) U26.J3(VSS) U26.J10(VSS) U26.J12(VSS) U26.K2(VSS) U26.K4(VSS) U26.K9(VSS) U26.K11(VSS) U26.N2(VSS) U26.N4(VSS) U26.N9(VSS) U26.N11(VSS) U26.P1(VSS) U26.P3(VSS) U26.P10(VSS) U26.P12(VSS) U26.T1(VSS) U26.T3(VSS) U26.T5(VSS) U26.T8(VSS) U26.T10(VSS) U26.T12(VSS) U26.V1(VSS) U26.V5(VSS) U26.V8(VSS) U26.V12(VSS) U26.W2(VSS) U26.W4(VSS) U26.W9(VSS) U26.W11(VSS) U26.Y1(VSS) U26.Y5(VSS) U26.Y8(VSS) U26.Y12(VSS) U56.2(GND) ; also on sheet 10 11 12 13 14 15 16 19 20 21 22 23 24 25 26 27 28 29 30 31 32 33 34 35 36 37 38 39 40 41 42 43 44
VCC1V8_SYS: C9.2 R9.2 R241.1 R262.1 R264.1 R273.1 R274.1 R275.1 R276.1 R277.1 U1.1(VCCA) ; also on sheet 13 19 21 34 37 39 40 42
VCC_3V3_SYS: C2.1 C3.2 C6.2 C17.2 C18.1 J2.2(3-3V) J2.4(3-3V) J2.72(3-3V) J2.74(3-3V) R2.2 R6.1 R22.2 R250.2 R272.1 U1.14(VCCB) ; also on sheet 10 11 13 14 19 20 22 23 24 26 27 29 30 31 33 34 35 36 37 38 39 40 41 42 43
VDD1_LPDDR4_1V8: C302.1 C309.1 C314.2 C322.1 C328.1 C345.1 C355.1 C363.1 C370.1 C374.1 C375.2 C378.1 FL12.2 U26.F1(VDD1) U26.F12(VDD1) U26.G4(VDD1) U26.G9(VDD1) U26.T4(VDD1) U26.T9(VDD1) U26.U1(VDD1) U26.U12(VDD1)
VDD_LPDDR4: C303.1 C304.1 C305.1 C306.1 C308.2 C315.1 C316.2 C320.1 C321.1 C323.1 C324.1 C325.1 C331.1 C332.1 C333.1 C335.1 C336.1 C337.1 C338.2 C341.1 C342.1 C343.1 C347.1 C348.1 C351.1 C352.1 C353.1 C359.1 C362.1 C364.1 C365.1 C366.1 C367.1 C369.2 C373.1 C377.1 R119.1 R122.1 R352.2 R369.2 R370.2 U26.A4(VDD2) U26.A9(VDD2) U26.AA3(VDDQ) U26.AA5(VDDQ) U26.AA8(VDDQ) U26.AA10(VDDQ) U26.AB4(VDD2) U26.AB9(VDD2) U26.B3(VDDQ) U26.B5(VDDQ) U26.B8(VDDQ) U26.B10(VDDQ) U26.D1(VDDQ) U26.D5(VDDQ) U26.D8(VDDQ) U26.D12(VDDQ) U26.F3(VDDQ) U26.F5(VDD2) U26.F8(VDD2) U26.F10(VDDQ) U26.H1(VDD2) U26.H5(VDD2) U26.H8(VDD2) U26.H12(VDD2) U26.K1(VDD2) U26.K3(VDD2) U26.K10(VDD2) U26.K12(VDD2) U26.N1(VDD2) U26.N3(VDD2) U26.N10(VDD2) U26.N12(VDD2) U26.R1(VDD2) U26.R5(VDD2) U26.R8(VDD2) U26.R12(VDD2) U26.U3(VDDQ) U26.U5(VDD2) U26.U8(VDD2) U26.U10(VDDQ) U26.W1(VDDQ) U26.W5(VDDQ) U26.W8(VDDQ) U26.W12(VDDQ) ; also on sheet 13 15 16
BT_EN_SOC: J2.54(W_DISABLE2#) R250.1 ; also on sheet 40
BT_UART_WAKE_SOC_1V8: R25.2 U1.3(A2)
BT_UART_WAKE_SOC_3V3: R22.1 R24.2 U1.12(B2) ; also on sheet 40
BT_UART_WAKE_SOC_R: J2.20(UART_WAKE#) R24.1 R25.1
BT_WLAN_EN: J2.56(W_DISABLE1#) R10.1 R11.2
COM_SDIO_CMD: J2.11(SDIO_CMD) R267.1
COM_SDIO_D0: J2.13(SDIO_DATA0) R269.1
COM_SDIO_D1: J2.15(SDIO_DATA1) R268.1
COM_SDIO_D2: J2.17(SDIO_DATA2) R266.1
COM_SDIO_D3: J2.19(SDIO_DATA3) R265.1
HFOSC0_CLKOUT_32K: R282.1 ; also on sheet 32
LPDDR4_CA0: U18.J5(DDR0_A0) U26.H2(CA0_A) U26.R2(CA0_B)
LPDDR4_CA1: U18.J2(DDR0_A1) U26.J2(CA1_A) U26.P2(CA1_B)
LPDDR4_CA2: U18.J4(DDR0_A2) U26.H9(CA2_A) U26.R9(CA2_B)
LPDDR4_CA3: U18.L4(DDR0_A3) U26.H10(CA3_A) U26.R10(CA3_B)
LPDDR4_CA4: U18.J1(DDR0_A4) U26.H11(CA4_A) U26.R11(CA4_B)
LPDDR4_CA5: U18.K5(DDR0_A5) U26.J11(CA5_A) U26.P11(CA5_B)
LPDDR4_CAL0: R349.1 U18.H6(DDR0_CAL0)
LPDDR4_CK_N: U18.L1(DDR0_CK0_N) U26.J9(CK_C_A) U26.P9(CK_C_B)
LPDDR4_CK_P: U18.M1(DDR0_CK0) U26.J8(CK_T_A) U26.P8(CK_T_B)
LPDDR4_CKE0: U18.P3(DDR0_CKE0) U26.J4(CKE0_A) U26.P4(CKE0_B)
LPDDR4_CKE1: U18.P5(DDR0_CKE1) U26.J5(CKE1_A) U26.P5(CKE1_B)
LPDDR4_CS0_A: U18.J6(DDR0_CS0_N) U26.H4(CS0_A)
LPDDR4_CS0_B: U18.M6(DDR0_RAS_N) U26.R4(CS0_B)
LPDDR4_CS1_A: U18.N4(DDR0_CS1_N) U26.H3(CS1_A)
LPDDR4_CS1_B: U18.M5(DDR0_CAS_N) U26.R3(CS1_B)
LPDDR4_DMI0: U18.C2(DDR0_DM0) U26.C3(DMI0_A)
LPDDR4_DMI1: U18.F3(DDR0_DM1) U26.C10(DMI1_A)
LPDDR4_DMI2: U18.U1(DDR0_DM2) U26.Y3(DMI0_B)
LPDDR4_DMI3: U18.W3(DDR0_DM3) U26.Y10(DMI1_B)
LPDDR4_DQ0: U18.A5(DDR0_DQ0) U26.B2(DQ0_A)
LPDDR4_DQ1: U18.B4(DDR0_DQ1) U26.C2(DQ1_A)
LPDDR4_DQ2: U18.B6(DDR0_DQ2) U26.E2(DQ2_A)
LPDDR4_DQ3: U18.D5(DDR0_DQ3) U26.F2(DQ3_A)
LPDDR4_DQ4: U18.C5(DDR0_DQ4) U26.F4(DQ4_A)
LPDDR4_DQ5: U18.C3(DDR0_DQ5) U26.E4(DQ5_A)
LPDDR4_DQ6: U18.B2(DDR0_DQ6) U26.C4(DQ6_A)
LPDDR4_DQ7: U18.A3(DDR0_DQ7) U26.B4(DQ7_A)
LPDDR4_DQ8: U18.E2(DDR0_DQ8) U26.B11(DQ8_A)
LPDDR4_DQ9: U18.F5(DDR0_DQ9) U26.C11(DQ9_A)
LPDDR4_DQ10: U18.E6(DDR0_DQ10) U26.E11(DQ10_A)
LPDDR4_DQ11: U18.G2(DDR0_DQ11) U26.F11(DQ11_A)
LPDDR4_DQ12: U18.G6(DDR0_DQ12) U26.F9(DQ12_A)
LPDDR4_DQ13: U18.G4(DDR0_DQ13) U26.E9(DQ13_A)
LPDDR4_DQ14: U18.E4(DDR0_DQ14) U26.C9(DQ14_A)
LPDDR4_DQ15: U18.D3(DDR0_DQ15) U26.B9(DQ15_A)
LPDDR4_DQ16: U18.T6(DDR0_DQ16) U26.AA2(DQ0_B)
LPDDR4_DQ17: U18.T4(DDR0_DQ17) U26.Y2(DQ1_B)
LPDDR4_DQ18: U18.U5(DDR0_DQ18) U26.V2(DQ2_B)
LPDDR4_DQ19: U18.R5(DDR0_DQ19) U26.U2(DQ3_B)
LPDDR4_DQ20: U18.P2(DDR0_DQ20) U26.U4(DQ4_B)
LPDDR4_DQ21: U18.R3(DDR0_DQ21) U26.V4(DQ5_B)
LPDDR4_DQ22: U18.T2(DDR0_DQ22) U26.Y4(DQ6_B)
LPDDR4_DQ23: U18.U3(DDR0_DQ23) U26.AA4(DQ7_B)
LPDDR4_DQ24: U18.Y2(DDR0_DQ24) U26.AA11(DQ8_B)
LPDDR4_DQ25: U18.V2(DDR0_DQ25) U26.Y11(DQ9_B)
LPDDR4_DQ26: U18.V4(DDR0_DQ26) U26.V11(DQ10_B)
LPDDR4_DQ27: U18.W5(DDR0_DQ27) U26.U11(DQ11_B)
LPDDR4_DQ28: U18.Y4(DDR0_DQ28) U26.U9(DQ12_B)
LPDDR4_DQ29: U18.AA3(DDR0_DQ29) U26.V9(DQ13_B)
LPDDR4_DQ30: U18.AA5(DDR0_DQ30) U26.Y9(DQ14_B)
LPDDR4_DQ31: U18.AB4(DDR0_DQ31) U26.AA9(DQ15_B)
LPDDR4_DQS0_N: U18.C1(DDR0_DQS0_N) U26.E3(DQS0_C_A)
LPDDR4_DQS0_P: U18.D1(DDR0_DQS0) U26.D3(DQS0_T_A)
LPDDR4_DQS1_N: U18.F1(DDR0_DQS1_N) U26.E10(DQS1_C_A)
LPDDR4_DQS1_P: U18.G1(DDR0_DQS1) U26.D10(DQS1_T_A)
LPDDR4_DQS2_N: U18.P1(DDR0_DQS2_N) U26.V3(DQS0_C_B)
LPDDR4_DQS2_P: U18.R1(DDR0_DQS2) U26.W3(DQS0_T_B)
LPDDR4_DQS3_N: U18.Y1(DDR0_DQS3_N) U26.V10(DQS1_C_B)
LPDDR4_DQS3_P: U18.W1(DDR0_DQS3) U26.W10(DQS1_T_B)
LPDDR4_ODT_CA_A: R370.1 U26.G2(ODT_CA_A)
LPDDR4_ODT_CA_B: R369.1 U26.T2(ODT_CA_B)
LPDDR4_RESET_N: R350.2 R352.1 U18.P6(DDR0_RESET0_N) U26.T11(RESET_N)
LPDDR4_ZQ0: R122.2 U26.A5(ZQ0)
LPDDR4_ZQ1: R119.2 U26.A8(ZQ1)
M2_LED1#: J2.6(LED_1#) TP95.1(TP)
M2_LED2#: J2.16(LED_2#) TP92.1(TP)
MCASP1_ACLKX_BT: J2.8(PCM_CLK/I2S_SCK) ; also on sheet 40
MCASP1_AFSX_BT: J2.10(PCM_SYNC/I2S_WS) ; also on sheet 40
MCASP1_AXR0_BT: J2.12(PCM_IN/I2S_SD_IN) R256.1 ; also on sheet 40
MCASP1_AXR2_BT: J2.14(PCM_OUT/I2S_SD_OUT) ; also on sheet 40
MMC2_CLK: J2.9(SDIO_CLK/SYSCLK) R241.2 R242.1 R244.1 ; also on sheet 19
MMC2_CMD: R259.2 R267.2 R275.2 ; also on sheet 19
MMC2_D0: R261.2 R269.2 R277.2 ; also on sheet 19
MMC2_D1: R260.2 R268.2 R276.2 ; also on sheet 19
MMC2_D2: R258.2 R266.2 R274.2 ; also on sheet 19
MMC2_D3: R257.2 R265.2 R273.2 ; also on sheet 19
SLOW_CLK: J2.50(SUSCLK_32kHz) R280.2 R282.2
SOC_DVDD1V8: FL12.1 ; also on sheet 13 15 16
SOC_UART1_CTS_BT: J2.34(UART_CTS) ; also on sheet 37
SOC_UART1_RTS_BT: J2.36(UART_RTS) ; also on sheet 37
SOC_UART1_RX_BT: J2.22(UART_RXD) ; also on sheet 37
SOC_UART1_TX_BT: R254.2 ; also on sheet 37
SoC_WLAN_SDIO_RST: U1.13(B1) ; also on sheet 40
USB_DM: J2.5(USB_D-) TP97.1(TP)
USB_DP: J2.3(USB_D+) TP98.1(TP)
WL_LT_EN: R6.2 R7.2 U1.8(OE) ; also on sheet 40
WLAN_ALERT_1V8: R8.2 U1.5(A4)
WLAN_ALERTn: R2.1 U1.10(B4) ; also on sheet 40
WLAN_EN: R11.1 R12.2 U1.4(A3) ; also on sheet 19
WLAN_EN_3V3: R10.2 U1.11(B3)
WLAN_IRQ: J2.21(SDIO_WAKE#) R262.2 ; also on sheet 19
WLAN_SDIO_RST: J2.23(SDIO_RESET#/TX_BLANKING) R9.1 U1.2(A1)
N15951749: C177.1 C584.1 R264.2 R272.2 U56.1(TRI-STATE) U56.4(VDD)
N15952254: R280.1 U56.3(OUTPUT)
N18121816: J21.2 R261.1
N18121892: J21.4 R260.1
N18121904: J21.6 R259.1
N18121916: J21.9 R244.2
N18121928: J21.12 R258.1
N18121940: J21.14 R257.1
N22734804: J2.32(UART_TXD) R254.1
N22816067: J2.62(ALERT#) R8.1

Not connected (* = marked no-connect by the designer): J2 35(PETP0)* 37(PETN0)* 38(VENDOR_DEFINED1)* 40(VENDOR_DEFINED2)* 41(PERP0)* 42(VENDOR_DEFINED3)* 43(PERN0)* 44(COEX3)* 46(COEX_RXD)* 47(REFCLKP0)* 48(COEX_TXD)* 49(REFCLKN0)* 52(PERST0#)* 53(CLKREQ0#)* 55(PEWAKE0#)* 58(I2C_DATA)* 59(RESERVED/PETP1)* 60(I2C_CLK)* 61(RESERVED/PETN1)* 64(RESERVED)* 65(RESERVED/PERP1)* 66(UIM_SWP/PERST1#)* 67(RESERVED/PERN1)* 68(UIM_POWER_SNK/CLKREQ1#)* 70(UIM_POWER_SRC/GPIO1/PEWAKE#)* 71(RESERVED/REFCLKP1)* 73(RESERVED/REFCLKN1)* SH3*; U1 6(NC1)* 9(NC2)*; U18 F6(RSVD3)* G7(RSVD5)* H2(DDR0_A7)* H3(DDR0_BA1)* H5(DDR0_ODT0)* H7(DDR0_ALERT_N)* K2(DDR0_A10)* K3(DDR0_A6)* K6(DDR0_BA0)* L2(DDR0_A9)* L5(DDR0_A11)* L6(DDR0_A8)* M2(DDR0_A13)* M3(DDR0_A12)* N2(DDR0_PAR)* N3(DDR0_ODT1)* N5(DDR0_ACT_N)* N6(DDR0_WE_N)* P4(DDR0_BG0)* R7(DDR0_BG1)*; U26 A1(DNU1)* A2(DNU2)* A11(DNU3)* A12(DNU4)* AA1(DNU7)* AA12(DNU8)* AB1(DNU9)* AB2(DNU10)* AB11(DNU11)* AB12(DNU12)* B1(DNU5)* B12(DNU6)* G11(NC1)* K5(NC2)* K8(NC3)* N5(NC4)* N8(NC5)*

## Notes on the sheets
sheet 17
- SOC LPDDR4 INTERFACE
- LPDDR4 POWER DECAPS
- VDDQ_LPDDR4_1V1
- R-Note:
  Verify the need to connect the
  NC pins on the custom board
  for memory expansion.
- VDD2_LPDDR4_1V1
- D-Note:
  RESERVED PINS
  Leave them unconnected
- LPDDR4 DEVICE
- VDDQ_LPDDR4_1V1
- VDD2_LPDDR4_1V1
- R-Note :
  Pulldown is populated
- D-Note :
  10 K pulldown is
  recommended
  Refer Processor specific
  DDR design guide
sheet 18
- M.2 INTERFACE - SDIO
- As per the connector specification
  Each Pin supports 1 Amp of current
- SoC_MAIN_UART1_RXD
- D-Note:
  Series resistors for the SDIO
  interface signals are optional
  on the custom board
- SoC_MAIN_UART1_TXD
- SoC_MAIN_UART1_CTS
- SoC_MAIN_UART1_RTS
- V
- C
- M.2 LEVEL TRANSLATOR
- C
- CAD Note :
  Place Series resistors for MMC2
  signals as TRI-PAD to avoid stub
- CAD Note :
  Place R280 & R282 close to
  each other to avoid stub.
- D-Note:
  Verify availability of pulls internal to the attached device
- V
- Design Note: WL_LT_EN = Active High
- V
- D-Note:
  R6 and R7 acts as a voltage divider to
  source 1.8V I/O pin (since OE refers to VCCA)
  from 3.3V output of I/O Expander.
